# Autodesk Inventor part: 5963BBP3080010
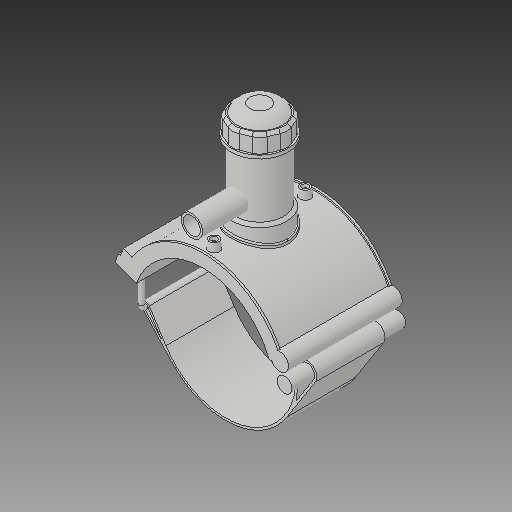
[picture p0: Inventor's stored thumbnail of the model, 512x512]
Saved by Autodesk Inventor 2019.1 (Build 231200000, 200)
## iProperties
Created: 2017-07
Part Number: 5963BBP3080010
Material: Generic
Description: PLASSON TAPPING SADDLE 8''IPS x 1''IPS
Document SubType Name: Modeling
Designer: KIM
Density: 1 g/cm^3
Appearance: Default
Author: KIM
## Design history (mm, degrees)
derived "5963BBP_5963BUP.ipt"
feature "Solid1::5963BBP_5963BUP.ipt"
feature "Solid2::5963BBP_5963BUP.ipt"
feature "Solid3::5963BBP_5963BUP.ipt"
tag "TaggingFeature1"
body "Solid1"
body "Solid2"
body "Solid3"
other parameters: "d_" = 218.7, "B_" = 179.832, "L_" = 176.022, "d_t" = 6, "H_2" = 177.038, "H_1" = 65.024, "d_1" = 33.3, "H_" = 104.902, "d1" = 253.692, "d148" = 3.2805, "d160" = 3.2805, "d169" = 3.2805, "d192" = 6.9984, "d0" = 218.7, "d2" = 269.748, "d3" = 54.675, "d4" = 176.022, "d5" = 0, "d6" = 0.1, "d8" = 0, "d19" = 6, "d20" = 6, "d21" = 105.6132, "d23" = 0, "d24" = 52.8066, "d26" = 0, "d27" = 3, "d28" = 3, "d29" = 3, "d30" = 72.9, "d31" = 6, "d32" = 0, "d33" = 0, "d34" = 0.6, "d40" = 131.91984, "d41" = 87.48, "d43" = 0, "d45" = 0, "d47" = 232.4592, "d70" = 15, "d72" = 0, "d73" = 6, "d75" = 5, "d76" = 0, "d77" = 10.935, "d78" = 139.35, "d79" = 15, "d80" = 70.4088, "d82" = 5 deg, "d84" = 4, "d85" = 14, "d86" = 0, "d87" = 3, "d88" = 0, "d89" = 1, "d90" = 1, "d91" = 140.8176, "d92" = 0, "d93" = 0.5, "d94" = 115.10526, "d96" = 258.76584, "d97" = 3.52044, "d98" = 0, "d102" = 2.187, "d120" = 140 deg, "d121" = 24.228, "d122" = 20 deg, "d123" = 507.384, "d124" = 152.2152, "d126" = 0, "d143" = 225.261, "d145" = 26.91692, "d149" = 3.2805, "d150" = 29.60862, "d153" = 176.022, "d154" = 0, "d156" = 126.846, "d157" = 160 deg, "d159" = 6.9984, "d161" = 3.2805, "d162" = 105.6132, "d163" = 0, "d164" = 109.35, "d167" = 21.87, "d168" = 123.7522, "d170" = 3.2805, "d172" = 0, "d173" = 1, "d175" = 109.35, "d176" = 20 deg, "d177" = 15.309, "d178" = 34.992, "d180" = 0, "d183" = 13.9968, "d184" = 12.2472, "d185" = 57.20715, "d186" = 57.20715, "d187" = 126.846, "d188" = 10.4976, "d189" = 15.309, "d190" = 0, "d191" = 190.269, "d193" = 6.9984, "d194" = 6.16077, "d195" = 90 deg, "d197" = 0, "d199" = 0, "d200" = 17.496, "d202" = 0, "d203" = 177.038, "d204" = 83.106, "d205" = 61.236, "d206" = 74.358, "d207" = 132.7785, "d208" = 138.08964, "d209" = 164.64534, "d210" = 75.2328, "d211" = 87.48, "d212" = 69.984, "d213" = 43.5366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
